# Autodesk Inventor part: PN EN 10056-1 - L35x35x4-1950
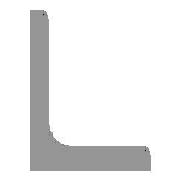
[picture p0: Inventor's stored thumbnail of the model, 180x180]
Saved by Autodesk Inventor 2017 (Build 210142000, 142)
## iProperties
Created: 2020-07
Part Number: PN EN 10056-1 - L35x35x4-1950
Material: Stal, miękka
Description: Kątownik równoramienny
Document SubType Name: Modeling
Standard: PN
Designer: X
Standards Organization: PN
Language: pl-PL
Size Designation: L35x35x4
Categories: <MemberInstance><Categories><Category DisplayName="Kształtowniki konstrukcyjne" InternalName="089c4875-fa83-4c05-b084-43b9cc11f5ed" Mnemonic="GRDR"><CategoryPar
Stock Number: L35x35x4
Density: 7.85 g/cm^3
Appearance: Częściowo polerowana
IsCustomPart: 1
_CCFamilyMember: 60
_CCFamilyDisplayName: PN EN 10056-1 (Kątownik równoramienny) - Kątownik równoramienny
_FrameMemberDoc: Frame Member File
_Version: 15.0.0
_GetPNFromCC: 1
Author: X
G_L: 1950,000 mm
G_W: 35,000 mm
G_H: 35,000 mm
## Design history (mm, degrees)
node "Płaszczyzna początkowa"
node "Płaszczyzna końcowa"
sketch "Szkic"
  geometry: L1 (-6.019, -1.019)-(-6.019, 22.481); L2 (-10.019, 24.981)-(-8.519, 24.981); L3 (-10.019, -10.019)-(-10.019, 24.981); L4 (-10.019, -10.019)-(24.981, -10.019); L5 (24.981, -8.519)-(24.981, -10.019); L6 (-1.019, -6.019)-(22.481, -6.019); L7 (0, 32.602)-(0, -17.123) reference; L8 (-17.123, 0)-(32.602, 0) reference; A1 r 5 centre (-1.019, -1.019) between (-6.019, -1.019) and (-1.019, -6.019); A2 r 2.5 centre (-8.519, 22.481) between (-6.019, 22.481) and (-8.519, 24.981); A3 r 2.5 centre (22.481, -8.519) between (24.981, -8.519) and (22.481, -6.019); 3 further points
  constraints: 12 end point, 6 point on circle, 6 point on line, 6 tangent, 3 centre point, 3 horizontal, 3 vertical, 1 equal radius
  dimensions: "d4" = 35 distance of L3.start L4.end (= b); "d6" = 35 distance of L3.start L2.start (= b); "d8" = 4 distance of point (24.981, -6.019) L4.end (= ParT); "d10" = 4 distance of L2.start point (-6.019, 24.981) (= ParT); "d17" = 5 radius of A1 (= R); "d18" = 2.5 radius of A2 (= R1); "d19" = 10.01931 distance between parallel lines of L8 L4 (= ex); "d20" = 10.01931 distance between parallel lines of L3 L7 (= d19)
extrude "Bryła" new body sketch "Szkic" stored distance "d11" = 1950 (= G_L); taper "d12" = 0 deg
node "Driven Length"
  sketch "Sketch3"
    geometry: L1 (0, 0)-(10, 0) reference
    constraints: 2 end point, 1 horizontal
  workplane "Work Plane10"
  sketch "Sketch4"
    geometry: L1 (-2, 0)-(12, 0) reference; L2 (-2, 1950)-(12, 1950) reference
    dimensions: "d24" = 1950 distance between parallel lines of L1 L2 (derived)
body "Solid1"
other parameters: "b" = 35 [user parameter; used in 3 equation terms], "ParT" = 4 [user parameter; used in 3 equation terms], "R" = 5 [user parameter; used in 1 equation term], "R1" = 2.5 [user parameter; used in 1 equation term], "G_L" = 1950 (= d24) [user parameter; used in 1 equation term], "d7" = 4 (derived), "d9" = 4 (derived), "ex" = 10.01931 (computed from b, ParT) [user parameter; used in 1 equation term], "G_OFFSET_START" = 0 [user parameter; used in 1 equation term], "G_OFFSET_END" = 0 [user parameter; used in 1 equation term], "d21" = 0 (computed from G_OFFSET_START), "d23" = 90 deg
